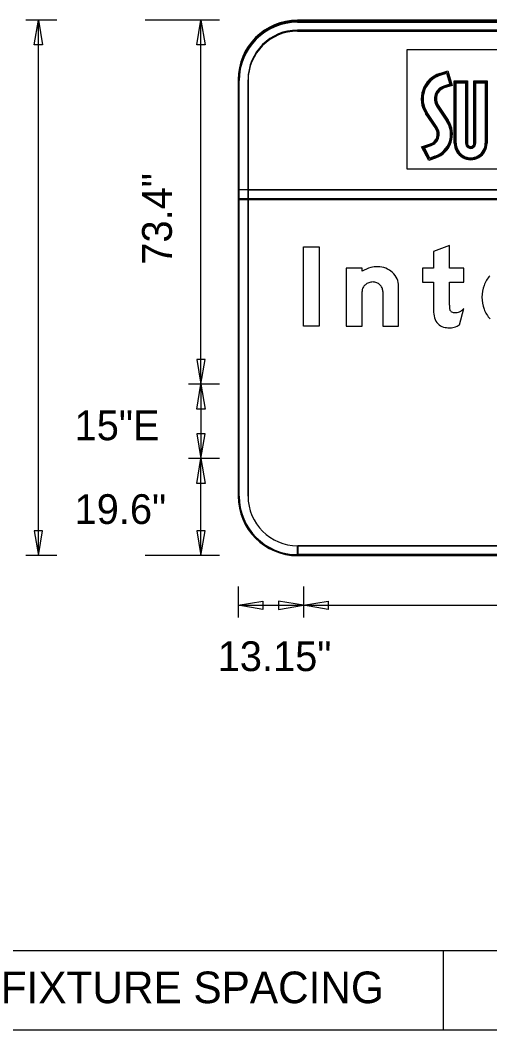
# Model space of a CAD drawing. Extents: x 122633 to 124574, y -23288 to -22025.
# Drawn here: x 124033.2 to 124127.9, y -22342 to -22138.4 of the extents above; entities that cross this region are included whole.
import ezdxf

# ---------------------------------------------------------------- set-up
doc = ezdxf.new("R2010")
doc.units = 0
for name, color, linetype in [('GSBWFill', 7, 'Continuous'), ('GSColorFill', 7, 'Continuous'), ('GSDims', 7, 'Continuous'), ('GSOutline', 7, 'Continuous'), ('Logo_dp', 7, 'Continuous'), ('SheetLinesMisc2_dp', 7, 'Continuous'), ('TextMinor', 7, 'Continuous')]:
    doc.layers.add(name, color=color, linetype=linetype)

msp = doc.modelspace()

# ---------------------------------------------------------------- linework, layer by layer
at = {"layer": 'GSBWFill'}
for p, q in [((124275.16, -22138.41), (124089.16, -22138.41)), ((124275.16, -22138.61), (124089.16, -22138.61)), ((124089.16, -22140.41), (124275.16, -22140.41)), ((124089.16, -22140.61), (124275.16, -22140.61)), ((124077.16, -22150.41), (124077.16, -22234.41)), ((124077.16, -22150.61), (124077.16, -22172.59)), ((124079.16, -22234.41), (124079.16, -22150.41)), ((124079.16, -22172.59), (124079.16, -22150.61)), ((124077.16, -22172.59), (124079.16, -22172.59)), ((124285.16, -22172.61), (124077.16, -22172.61)), ((124077.16, -22172.61), (124077.16, -22174.61)), ((124077.16, -22174.61), (124287.16, -22174.61)), ((124106.32, -22193.12), (124106.32, -22200.14)), ((124121.8, -22199.84), (124122.64, -22196.53)), ((124089.16, -22246.41), (124089.16, -22244.41)), ((124275.16, -22244.41), (124089.18, -22244.41)), ((124089.18, -22244.41), (124089.18, -22246.41)), ((124089.18, -22246.41), (124275.16, -22246.41))]:
    msp.add_line(p, q, dxfattribs=at)
msp.add_lwpolyline([(124090.32, -22184.14), (124093.52, -22184.14), (124093.52, -22200.14), (124090.32, -22200.14)], close=True, dxfattribs=at)
for points in [[(124119.76, -22195.9), (124119.76, -22191.22), (124122.64, -22191.22), (124122.64, -22188.46), (124119.76, -22188.46), (124119.76, -22183.86), (124116.56, -22185.07), (124116.56, -22188.46), (124114.32, -22188.46), (124114.32, -22191.22), (124116.56, -22191.22), (124116.56, -22196.87)], [(124102.16, -22189.04), (124102.16, -22188.46), (124098.96, -22188.46), (124098.96, -22200.14), (124102.16, -22200.14), (124102.16, -22193.12)], [(124106.32, -22200.14), (124109.52, -22200.14), (124109.52, -22192.07)]]:
    msp.add_lwpolyline(points, dxfattribs=at)
for centre, radius, start, end in [((124089.16, -22150.41), 12, 90, 180), ((124089.16, -22150.61), 12, 90, 180), ((124089.16, -22150.41), 10, 90, 180), ((124089.16, -22150.61), 10, 90, 180), ((124089.16, -22234.41), 12, 180, 270), ((124089.16, -22234.41), 10, 180, 270)]:
    msp.add_arc(centre, radius, start, end, dxfattribs=at)
for centre, major_axis, ratio, start_param, end_param in [((124105.26, -22193.9), (0, 5.76), 0.999997, 0.235088, 0.567132), ((124105.31, -22194.54), (0, 6.4), 0.999997, 0, 0.219986), ((124105.31, -22192.64), (0, 4.5), 0.999997, 5.914285, 6.283185), ((124105.42, -22192.36), (0, 4.2), 0.999997, 5.532258, 5.914285), ((124105.59, -22192.18), (0, 3.96), 0.999997, 5.130076, 5.532258), ((124105.85, -22192.07), (0, 3.67), 0.999997, 4.712389, 5.130076), ((124132.55, -22194.01), (0, 6.17), 0.999994, 0.851746, 1.222943), ((124103.83, -22193.12), (0, 1.67), 0.999997, 1.126231, 1.570796), ((124104.08, -22193.24), (0, 1.95), 0.999997, 0.715718, 1.126231), ((124104.25, -22193.43), (0, 2.2), 0.999997, 0.345704, 0.715718), ((124104.36, -22193.73), (0, 2.52), 0.999997, 0, 0.345704), ((124104.36, -22193.23), (0, 2.02), 0.999997, 5.900624, 6.283185), ((124104.38, -22193.18), (0, 1.96), 0.999997, 5.51227, 5.900624), ((124104.41, -22193.14), (0, 1.91), 0.999997, 5.115435, 5.51227), ((124104.47, -22193.12), (0, 1.86), 0.999997, 4.712389, 5.115435), ((124133.34, -22194.3), (0, 7.02), 0.999994, 1.222943, 1.570796), ((124133.13, -22194.3), (0, 6.81), 0.999994, 1.570796, 1.928626), ((124122.77, -22196.87), (0, 6.21), 0.999998, 1.570796, 1.830698), ((124139.79, -22195.9), (0, 20.03), 0.999998, 1.570796, 1.606005), ((124120.68, -22196.45), (0, 0.92), 0.999998, 1.74085, 2.407828), ((124120.71, -22196.42), (0, 0.963), 0.999998, 2.407828, 3.141593), ((124121.36, -22196.12), (0, 1.2), 0.999998, 3.310762, 3.756278), ((124120.53, -22194.96), (0, 2.63), 0.999998, 3.756278, 4.071638), ((124132.52, -22194.53), (0, 6.16), 0.999994, 1.928626, 2.305123), ((124119.28, -22197.79), (0, 2.6), 0.999998, 1.830698, 2.869526), ((124120.71, -22192.33), (0, 5.05), 0.999998, 3.141593, 3.310762), ((124119.76, -22196.08), (0, 4.38), 0.999998, 2.869526, 3.141593), ((124119.76, -22194.15), (0, 6.31), 0.999998, 3.141593, 3.205734), ((124120, -22197.85), (0, 2.6), 0.999998, 3.205734, 3.427755), ((124119.66, -22196.69), (0, 3.81), 0.999998, 3.427755, 3.738844)]:
    msp.add_ellipse(centre, major_axis=major_axis, ratio=ratio, start_param=start_param, end_param=end_param, dxfattribs=at)
at = {"layer": 'GSColorFill'}
for p, q in [((124275.16, -22138.41), (124089.16, -22138.41)), ((124275.16, -22138.41), (124089.16, -22138.41)), ((124275.16, -22138.41), (124089.16, -22138.41)), ((124089.16, -22138.61), (124275.16, -22138.61)), ((124275.16, -22138.61), (124089.16, -22138.61)), ((124275.16, -22138.61), (124089.16, -22138.61)), ((124275.16, -22138.61), (124089.16, -22138.61)), ((124089.16, -22138.81), (124275.16, -22138.81)), ((124089.16, -22140.41), (124275.16, -22140.41)), ((124089.16, -22140.61), (124275.16, -22140.61)), ((124077.16, -22150.41), (124077.16, -22234.41)), ((124077.16, -22150.41), (124077.16, -22234.41)), ((124077.16, -22150.41), (124077.16, -22234.41)), ((124077.16, -22150.61), (124077.16, -22174.61)), ((124077.16, -22150.61), (124077.16, -22172.59)), ((124077.16, -22150.61), (124077.16, -22174.41)), ((124077.36, -22234.41), (124077.36, -22150.41)), ((124077.36, -22174.41), (124077.36, -22150.61)), ((124079.16, -22234.41), (124079.16, -22150.41)), ((124079.16, -22172.59), (124079.16, -22150.61)), ((124077.16, -22172.59), (124079.16, -22172.59)), ((124285.16, -22172.61), (124077.16, -22172.61)), ((124077.16, -22172.61), (124077.16, -22174.61)), ((124077.16, -22174.41), (124077.36, -22174.41)), ((124286.96, -22174.41), (124077.16, -22174.41)), ((124077.16, -22174.41), (124077.16, -22174.61)), ((124077.16, -22174.61), (124287.16, -22174.61)), ((124077.16, -22174.61), (124287.16, -22174.61)), ((124077.16, -22174.61), (124287.16, -22174.61)), ((124106.32, -22193.12), (124106.32, -22200.14)), ((124121.8, -22199.84), (124122.64, -22196.53)), ((124089.16, -22246.41), (124089.16, -22244.41)), ((124275.16, -22244.41), (124089.18, -22244.41)), ((124089.18, -22244.41), (124089.18, -22246.41)), ((124089.16, -22246.41), (124089.16, -22246.21)), ((124275.16, -22246.21), (124089.16, -22246.21)), ((124089.16, -22246.21), (124089.16, -22246.41)), ((124089.16, -22246.41), (124275.16, -22246.41)), ((124089.16, -22246.41), (124275.16, -22246.41)), ((124089.18, -22246.41), (124275.16, -22246.41))]:
    msp.add_line(p, q, dxfattribs=at)
msp.add_lwpolyline([(124090.32, -22184.14), (124093.52, -22184.14), (124093.52, -22200.14), (124090.32, -22200.14)], close=True, dxfattribs=at)
for points in [[(124119.76, -22195.9), (124119.76, -22191.22), (124122.64, -22191.22), (124122.64, -22188.46), (124119.76, -22188.46), (124119.76, -22183.86), (124116.56, -22185.07), (124116.56, -22188.46), (124114.32, -22188.46), (124114.32, -22191.22), (124116.56, -22191.22), (124116.56, -22196.87)], [(124102.16, -22189.04), (124102.16, -22188.46), (124098.96, -22188.46), (124098.96, -22200.14), (124102.16, -22200.14), (124102.16, -22193.12)], [(124106.32, -22200.14), (124109.52, -22200.14), (124109.52, -22192.07)]]:
    msp.add_lwpolyline(points, dxfattribs=at)
for centre, radius, start, end in [((124089.16, -22150.41), 12, 90, 180), ((124089.16, -22150.41), 12, 90, 180), ((124089.16, -22150.41), 12, 90, 180), ((124089.16, -22150.61), 12, 90, 180), ((124089.16, -22150.61), 12, 90, 180), ((124089.16, -22150.61), 12, 90, 180), ((124089.16, -22150.41), 11.8, 90, 180), ((124089.16, -22150.61), 11.8, 90, 180), ((124089.16, -22150.41), 10, 90, 180), ((124089.16, -22150.61), 10, 90, 180), ((124089.16, -22234.41), 12, 180, 270), ((124089.16, -22234.41), 12, 180, 270), ((124089.16, -22234.41), 12, 180, 270), ((124089.16, -22234.41), 11.8, 180, 270), ((124089.16, -22234.41), 10, 180, 270)]:
    msp.add_arc(centre, radius, start, end, dxfattribs=at)
for centre, major_axis, ratio, start_param, end_param in [((124105.26, -22193.9), (0, 5.76), 0.999997, 0.235088, 0.567132), ((124105.31, -22194.54), (0, 6.4), 0.999997, 0, 0.219986), ((124105.31, -22192.64), (0, 4.5), 0.999997, 5.914285, 6.283185), ((124105.42, -22192.36), (0, 4.2), 0.999997, 5.532258, 5.914285), ((124105.59, -22192.18), (0, 3.96), 0.999997, 5.130076, 5.532258), ((124105.85, -22192.07), (0, 3.67), 0.999997, 4.712389, 5.130076), ((124132.55, -22194.01), (0, 6.17), 0.999994, 0.851746, 1.222943), ((124103.83, -22193.12), (0, 1.67), 0.999997, 1.126231, 1.570796), ((124104.08, -22193.24), (0, 1.95), 0.999997, 0.715718, 1.126231), ((124104.25, -22193.43), (0, 2.2), 0.999997, 0.345704, 0.715718), ((124104.36, -22193.73), (0, 2.52), 0.999997, 0, 0.345704), ((124104.36, -22193.23), (0, 2.02), 0.999997, 5.900624, 6.283185), ((124104.38, -22193.18), (0, 1.96), 0.999997, 5.51227, 5.900624), ((124104.41, -22193.14), (0, 1.91), 0.999997, 5.115435, 5.51227), ((124104.47, -22193.12), (0, 1.86), 0.999997, 4.712389, 5.115435), ((124133.34, -22194.3), (0, 7.02), 0.999994, 1.222943, 1.570796), ((124133.13, -22194.3), (0, 6.81), 0.999994, 1.570796, 1.928626), ((124122.77, -22196.87), (0, 6.21), 0.999998, 1.570796, 1.830698), ((124139.79, -22195.9), (0, 20.03), 0.999998, 1.570796, 1.606005), ((124120.68, -22196.45), (0, 0.92), 0.999998, 1.74085, 2.407828), ((124120.71, -22196.42), (0, 0.963), 0.999998, 2.407828, 3.141593), ((124121.36, -22196.12), (0, 1.2), 0.999998, 3.310762, 3.756278), ((124120.53, -22194.96), (0, 2.63), 0.999998, 3.756278, 4.071638), ((124132.52, -22194.53), (0, 6.16), 0.999994, 1.928626, 2.305123), ((124119.28, -22197.79), (0, 2.6), 0.999998, 1.830698, 2.869526), ((124120.71, -22192.33), (0, 5.05), 0.999998, 3.141593, 3.310762), ((124119.76, -22196.08), (0, 4.38), 0.999998, 2.869526, 3.141593), ((124119.76, -22194.15), (0, 6.31), 0.999998, 3.141593, 3.205734), ((124120, -22197.85), (0, 2.6), 0.999998, 3.205734, 3.427755), ((124119.66, -22196.69), (0, 3.81), 0.999998, 3.427755, 3.738844)]:
    msp.add_ellipse(centre, major_axis=major_axis, ratio=ratio, start_param=start_param, end_param=end_param, dxfattribs=at)
at = {"layer": 'GSDims'}
for p, q in [((124040.64, -22138.41), (124034.39, -22138.41)), ((124036.89, -22246.41), (124036.89, -22138.41)), ((124073.41, -22138.41), (124058.41, -22138.41)), ((124073.41, -22138.41), (124067.16, -22138.41)), ((124069.66, -22211.84), (124069.66, -22138.41)), ((124073.41, -22211.84), (124067.16, -22211.84)), ((124073.41, -22211.84), (124067.16, -22211.84)), ((124069.66, -22211.84), (124069.66, -22226.84)), ((124073.41, -22226.84), (124067.16, -22226.84)), ((124073.41, -22226.84), (124067.16, -22226.84)), ((124069.66, -22246.41), (124069.66, -22226.84)), ((124040.64, -22246.41), (124034.39, -22246.41)), ((124073.41, -22246.41), (124058.41, -22246.41)), ((124073.41, -22246.41), (124067.16, -22246.41)), ((124077.16, -22252.66), (124077.16, -22258.91)), ((124077.16, -22252.66), (124077.16, -22258.91)), ((124090.32, -22252.66), (124090.32, -22258.91)), ((124090.32, -22252.66), (124090.32, -22258.91)), ((124077.16, -22256.41), (124090.32, -22256.41)), ((124090.32, -22256.41), (124274, -22256.41))]:
    msp.add_line(p, q, dxfattribs=at)
for points in [[(124036.89, -22138.41), (124037.72, -22143.41), (124036.05, -22143.41)], [(124069.66, -22138.41), (124070.49, -22143.41), (124068.83, -22143.41)], [(124069.66, -22211.84), (124070.49, -22206.84), (124068.83, -22206.84)], [(124069.66, -22211.84), (124070.49, -22216.84), (124068.83, -22216.84)], [(124069.66, -22226.84), (124070.49, -22221.84), (124068.83, -22221.84)], [(124069.66, -22226.84), (124070.49, -22231.84), (124068.83, -22231.84)], [(124036.89, -22246.41), (124037.72, -22241.41), (124036.05, -22241.41)], [(124069.66, -22246.41), (124070.49, -22241.41), (124068.83, -22241.41)], [(124077.16, -22256.41), (124082.16, -22255.58), (124082.16, -22257.25)], [(124090.32, -22256.41), (124085.32, -22255.58), (124085.32, -22257.25)], [(124090.32, -22256.41), (124095.32, -22255.58), (124095.32, -22257.25)]]:
    msp.add_lwpolyline(points, close=True, dxfattribs=at)
at = {"layer": 'GSOutline'}
for p, q in [((124275.16, -22138.41), (124089.16, -22138.41)), ((124275.16, -22138.61), (124089.16, -22138.61)), ((124275.16, -22140.41), (124089.16, -22140.41)), ((124275.16, -22140.61), (124089.16, -22140.61)), ((124077.16, -22150.41), (124077.16, -22234.41)), ((124077.16, -22150.61), (124077.16, -22174.61)), ((124079.16, -22150.41), (124079.16, -22234.41)), ((124079.16, -22150.61), (124079.16, -22172.61)), ((124079.16, -22172.61), (124285.16, -22172.61)), ((124077.16, -22174.61), (124287.16, -22174.61)), ((124106.32, -22193.12), (124106.32, -22200.14)), ((124121.8, -22199.84), (124122.64, -22196.53)), ((124089.16, -22244.41), (124275.16, -22244.41)), ((124089.16, -22246.41), (124275.16, -22246.41))]:
    msp.add_line(p, q, dxfattribs=at)
msp.add_lwpolyline([(124090.32, -22184.14), (124093.52, -22184.14), (124093.52, -22200.14), (124090.32, -22200.14)], close=True, dxfattribs=at)
for points in [[(124119.76, -22195.9), (124119.76, -22191.22), (124122.64, -22191.22), (124122.64, -22188.46), (124119.76, -22188.46), (124119.76, -22183.86), (124116.56, -22185.07), (124116.56, -22188.46), (124114.32, -22188.46), (124114.32, -22191.22), (124116.56, -22191.22), (124116.56, -22196.87)], [(124102.16, -22189.04), (124102.16, -22188.46), (124098.96, -22188.46), (124098.96, -22200.14), (124102.16, -22200.14), (124102.16, -22193.12)], [(124106.32, -22200.14), (124109.52, -22200.14), (124109.52, -22192.07)]]:
    msp.add_lwpolyline(points, dxfattribs=at)
for centre, radius, start, end in [((124089.16, -22150.41), 12, 90, 180), ((124089.16, -22150.61), 12, 90, 180), ((124089.16, -22150.41), 10, 90, 180), ((124089.16, -22150.61), 10, 90, 180), ((124089.16, -22234.41), 12, 180, 270), ((124089.16, -22234.41), 10, 180, 270)]:
    msp.add_arc(centre, radius, start, end, dxfattribs=at)
for centre, major_axis, ratio, start_param, end_param in [((124105.26, -22193.9), (0, 5.76), 0.999997, 0.235088, 0.567132), ((124105.31, -22194.54), (0, 6.4), 0.999997, 0, 0.219986), ((124105.31, -22192.64), (0, 4.5), 0.999997, 5.914285, 6.283185), ((124105.42, -22192.36), (0, 4.2), 0.999997, 5.532258, 5.914285), ((124105.59, -22192.18), (0, 3.96), 0.999997, 5.130076, 5.532258), ((124105.85, -22192.07), (0, 3.67), 0.999997, 4.712389, 5.130076), ((124132.55, -22194.01), (0, 6.17), 0.999994, 0.851746, 1.222943), ((124103.83, -22193.12), (0, 1.67), 0.999997, 1.126231, 1.570796), ((124104.08, -22193.24), (0, 1.95), 0.999997, 0.715718, 1.126231), ((124104.25, -22193.43), (0, 2.2), 0.999997, 0.345704, 0.715718), ((124104.36, -22193.73), (0, 2.52), 0.999997, 0, 0.345704), ((124104.36, -22193.23), (0, 2.02), 0.999997, 5.900624, 6.283185), ((124104.38, -22193.18), (0, 1.96), 0.999997, 5.51227, 5.900624), ((124104.41, -22193.14), (0, 1.91), 0.999997, 5.115435, 5.51227), ((124104.47, -22193.12), (0, 1.86), 0.999997, 4.712389, 5.115435), ((124133.34, -22194.3), (0, 7.02), 0.999994, 1.222943, 1.570796), ((124133.13, -22194.3), (0, 6.81), 0.999994, 1.570796, 1.928626), ((124122.77, -22196.87), (0, 6.21), 0.999998, 1.570796, 1.830698), ((124139.79, -22195.9), (0, 20.03), 0.999998, 1.570796, 1.606005), ((124120.68, -22196.45), (0, 0.92), 0.999998, 1.74085, 2.407828), ((124120.71, -22196.42), (0, 0.963), 0.999998, 2.407828, 3.141593), ((124121.36, -22196.12), (0, 1.2), 0.999998, 3.310762, 3.756278), ((124120.53, -22194.96), (0, 2.63), 0.999998, 3.756278, 4.071638), ((124132.52, -22194.53), (0, 6.16), 0.999994, 1.928626, 2.305123), ((124119.28, -22197.79), (0, 2.6), 0.999998, 1.830698, 2.869526), ((124120.71, -22192.33), (0, 5.05), 0.999998, 3.141593, 3.310762), ((124119.76, -22196.08), (0, 4.38), 0.999998, 2.869526, 3.141593), ((124119.76, -22194.15), (0, 6.31), 0.999998, 3.141593, 3.205734), ((124120, -22197.85), (0, 2.6), 0.999998, 3.205734, 3.427755), ((124119.66, -22196.69), (0, 3.81), 0.999998, 3.427755, 3.738844)]:
    msp.add_ellipse(centre, major_axis=major_axis, ratio=ratio, start_param=start_param, end_param=end_param, dxfattribs=at)
at = {"layer": 'Logo_dp'}
for p, q in [((124117.8, -22149.17), (124119.42, -22148.65)), ((124117.86, -22149.35), (124119.3, -22148.89)), ((124117.91, -22149.53), (124119.18, -22149.13)), ((124119.18, -22149.13), (124119.86, -22151.31)), ((124119.3, -22148.89), (124120.1, -22151.44)), ((124119.42, -22148.65), (124120.34, -22151.56)), ((124119.86, -22151.31), (124118.6, -22151.71)), ((124120.1, -22151.44), (124118.66, -22151.89)), ((124120.34, -22151.56), (124118.71, -22152.07)), ((124120.74, -22163.23), (124120.74, -22150.65)), ((124120.74, -22150.65), (124123.4, -22150.65)), ((124120.93, -22163.23), (124120.93, -22150.84)), ((124120.93, -22150.84), (124123.21, -22150.84)), ((124121.12, -22163.23), (124121.12, -22151.03)), ((124121.12, -22151.03), (124123.02, -22151.03)), ((124123.02, -22151.03), (124123.02, -22163.23)), ((124123.21, -22150.84), (124123.21, -22163.23)), ((124123.4, -22150.65), (124123.4, -22163.23)), ((124124.7, -22163.23), (124124.7, -22150.65)), ((124124.7, -22150.65), (124127.36, -22150.65)), ((124124.89, -22163.23), (124124.89, -22150.84)), ((124124.89, -22150.84), (124127.17, -22150.84)), ((124125.08, -22163.23), (124125.08, -22151.03)), ((124125.08, -22151.03), (124126.98, -22151.03)), ((124126.98, -22151.03), (124126.98, -22163.23)), ((124127.17, -22150.84), (124127.17, -22163.23)), ((124127.36, -22150.65), (124127.36, -22163.23)), ((124117.18, -22155.76), (124119.2, -22158.8)), ((124117.34, -22155.65), (124119.36, -22158.7)), ((124117.5, -22155.55), (124119.52, -22158.59)), ((124116.99, -22160.28), (124114.97, -22157.24)), ((124117.15, -22160.18), (124115.12, -22157.13)), ((124117.3, -22160.07), (124115.28, -22157.03)), ((124114.16, -22163.96), (124115.97, -22163.33)), ((124115.61, -22166.68), (124114.16, -22163.96)), ((124114.44, -22164.06), (124116.03, -22163.51)), ((124115.7, -22166.45), (124114.44, -22164.06)), ((124114.71, -22164.17), (124116.09, -22163.69)), ((124115.79, -22166.21), (124114.71, -22164.17)), ((124116.97, -22166.21), (124115.61, -22166.68)), ((124116.91, -22166.03), (124115.7, -22166.45)), ((124116.84, -22165.85), (124115.79, -22166.21))]:
    msp.add_line(p, q, dxfattribs=at)
msp.add_lwpolyline([(124111.16, -22168.41), (124177.82, -22168.41), (124177.82, -22144.41), (124111.16, -22144.41)], close=True, dxfattribs=at)
for centre, major_axis, start_param, end_param in [((124119.41, -22154.27), (0, 5.35), 0.305879, 2.158799), ((124119.41, -22154.27), (0, 5.16), 0.305879, 2.158799), ((124119.41, -22154.27), (0, 4.97), 0.305879, 2.158799), ((124119.41, -22154.27), (0, 2.68), 0.305879, 2.158799), ((124119.41, -22154.27), (0, 2.49), 0.305879, 2.158799), ((124119.41, -22154.27), (0, 2.3), 0.305879, 2.158799), ((124115.3, -22161.41), (0, -2.03), 0.334742, 2.158799), ((124115.3, -22161.41), (0, -2.22), 0.334742, 2.158799), ((124115.3, -22161.41), (0, -2.41), 0.334742, 2.158799), ((124115.3, -22161.41), (0, -4.7), 0.334737, 2.158799), ((124115.3, -22161.41), (0, -4.89), 0.334737, 2.158799), ((124115.3, -22161.41), (0, -5.08), 0.334737, 2.158799), ((124124.05, -22163.23), (0, -3.32), 4.712389, 7.853982), ((124124.05, -22163.23), (0, -3.13), 4.712389, 7.853982), ((124124.05, -22163.23), (0, -2.94), 4.712389, 7.853982), ((124124.05, -22163.23), (0, -1.03), 4.712389, 7.853982), ((124124.05, -22163.23), (0, -0.839), 4.712389, 7.853982), ((124124.05, -22163.23), (0, -0.648), 4.712389, 7.853982)]:
    msp.add_ellipse(centre, major_axis=major_axis, ratio=0.997, start_param=start_param, end_param=end_param, dxfattribs=at)
at = {"layer": 'SheetLinesMisc2_dp'}
for p, q in [((123883.65, -22326.02), (124497.63, -22326.02)), ((124118.51, -22326.02), (124118.51, -22342.04)), ((123883.65, -22342.04), (124497.63, -22342.04))]:
    msp.add_line(p, q, dxfattribs=at)

# ---------------------------------------------------------------- texts
at = {"layer": 'GSDims'}
msp.add_text('73.4"', height=6, rotation=90, dxfattribs=at).set_placement((124063.8, -22187.72))
for s, p in [('15"E', (124044.19, -22223.13)), ('19.6"', (124044.19, -22240.02)), ('13.15"', (124073.04, -22269.69))]:
    msp.add_text(s, height=6, dxfattribs=at).set_placement(p)
at = {"layer": 'TextMinor'}
msp.add_text('FIXTURE SPACING', height=6.3774, dxfattribs=at).set_placement((124029.3, -22336.67))

doc.saveas('drawing.dxf')
